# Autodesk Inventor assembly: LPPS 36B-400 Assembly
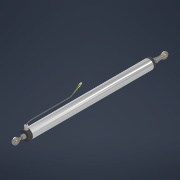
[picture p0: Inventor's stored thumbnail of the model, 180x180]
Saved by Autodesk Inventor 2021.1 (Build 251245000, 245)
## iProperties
Created: 2020-09
Part Number: LPPS 36B-400 Assembly
Document SubType Name: Assembly
Designer: J. Nielson
Author: J. Nielson
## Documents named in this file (3)
- C:\Users\Justin\Documents\CAD\The Sensor Connection\LPPS\LPPS-36B Series\3D\LPPS 36B-400\LPPS 36B-400 Assembly.iam
- C:\Users\Justin\Documents\CAD\The Sensor Connection\LPPS\LPPS-36B Series\3D\LPPS 36B-400\LPPS 36B-400 Shaft_Shrinkwrap.ipt
- C:\Users\Justin\Documents\CAD\The Sensor Connection\LPPS\LPPS-36B Series\3D\LPPS 36B-400\LPPS 36B-400_Shrinkwrap.ipt
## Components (2 placed, 2 different names)
1. LPPS 36B-400 Shaft_Shrinkwrap:1 — Mate:1, Angle:1, Cylindrical:1
2. LPPS 36B-400_Shrinkwrap:1 — Mate:1, Cylindrical:1
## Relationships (3: Mate 1, Angle 1, CylindricalJoint 1)
- Mate:1: LPPS 36B-400 Shaft_Shrinkwrap:1 ↔ LPPS 36B-400_Shrinkwrap:1
- Angle:1: LPPS 36B-400 Shaft_Shrinkwrap:1
- Cylindrical:1: LPPS 36B-400 Shaft_Shrinkwrap:1 ↔ LPPS 36B-400_Shrinkwrap:1
